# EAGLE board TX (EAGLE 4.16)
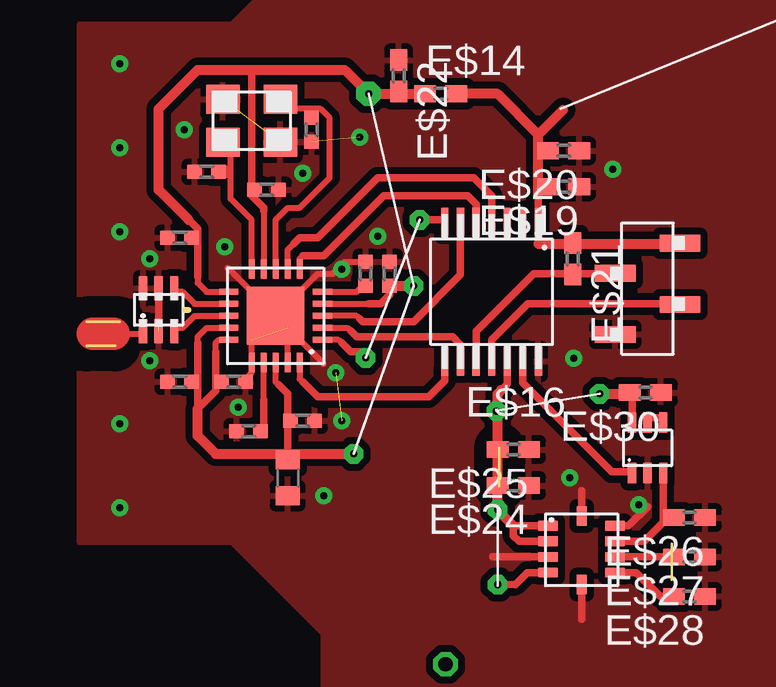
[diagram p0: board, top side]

Size 24.38 x 11.25 mm. Coordinates in mm from the lower left corner, seen from the top.
Outline: 4.12,11.25 4.25,11.25
Outline: 1.19,9.75 0,9.75
Outline: 1.38,10.75 0,10.75
Outline: 24.38,1.5 24.38,0
Outline: 17.2,5.5 17.2,3.9
Copper layers (1*16): Top 0.035mm / dielectric 1.5mm / Bottom 0.035mm
Design rules "default": minimum track width 10mil, minimum drill 24mil, track to track 8mil, track to pad 8mil, pad to pad 8mil, via to via 8mil, smd to smd 8mil, copper to edge 40mil, drill to drill 8mil, minimum pad ring 10mil, minimum via ring 8mil, stop-mask expansion 4mil, vias tented up to drill 0mil, thermal gap 10mil

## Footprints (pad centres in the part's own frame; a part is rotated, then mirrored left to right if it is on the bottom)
QFN20 = smd 0.8 x 0.26: 1 -1.95,1; 2 -1.95,0.5; 3 -1.95,0; 4 -1.95,-0.5; 5 -1.95,-1; 11 1.95,-1; 12 1.95,-0.5; 13 1.95,0; 14 1.95,0.5; 15 1.95,1 | smd 0.26 x 0.8: 6 -1,-1.95; 7 -0.5,-1.95; 8 0,-1.95; 9 0.5,-1.95; 10 1,-1.95; 16 1,1.95; 17 0.5,1.95; 18 0,1.95; 19 -0.5,1.95; 20 -1,1.95 | smd 2.4 x 2.4: EP 0,0
BALUN = smd 1 x 0.35: 1 -0.9,0.65; 2 -0.9,0; 3 -0.9,-0.65; 4 0.9,-0.65; 5 0.9,0; 6 0.9,0.65
NX3225GA = smd 1.4 x 1.2: 1 -1.2,-0.9; 2 1.2,-0.9; 3 1.2,0.9; 4 -1.2,0.9
C0402N = smd 0.6 x 0.6: 1 0.5,0; 2 -0.5,0
C0402 = smd 0.9 x 0.7: 1 -0.65,0; 2 0.65,0
C0603N = smd 0.8 x 1: 1 -0.75,0; 2 0.75,0
PW14 = smd 0.3 x 1.2: 1 -1.95,-2.9; 2 -1.3,-2.9; 3 -0.65,-2.9; 4 0,-2.9; 5 0.65,-2.9; 6 1.3,-2.9; 7 1.95,-2.9; 8 1.95,2.9; 9 1.3,2.9; 10 0.65,2.9; 11 0,2.9; 12 -0.65,2.9; 13 -1.3,2.9; 14 -1.95,2.9
1/2AA = drill 1 pad 3.1 octagon: P$1 14.7,0; P$2 -14.7,0 | drill 0.5 pad 1.27 round: P$3 -7.3,0; P$4 7.3,0 | hole 3.2: 7.3,0; -7.3,0
HEADERS4 = smd 0.7 x 1.7: P$1 1.27,1.35; P$3 -1.28,1.35; P$4 -0.03,-1.35; P$5 2.52,-1.35
KXTC9-2050 = smd 0.813 x 0.406: 1 -1.4,0.65; 2 -1.4,0; 3 -1.4,-0.65; 4 -1.4,-1.3; 6 1.4,-1.3; 7 1.4,-0.65; 8 1.4,0; 9 1.4,0.65 | smd 0.406 x 0.813: 5 0,-1.8; 10 0,1.05
SOT363 = smd 0.35 x 0.85: 1 -0.65,-1.05; 2 0,-1.05; 3 0.65,-1.05; 4 0.65,1.05; 5 0,1.05; 6 -0.65,1.05

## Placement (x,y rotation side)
E$1  [QFN20]  7.88,11 180 top
E$2  [BALUN]  3,11.25 90 top
E$3  [NX3225GA]  not placed on the board
E$4  [C0402N]  11.62,12.75 90 top
E$5  [C0402N]  not placed on the board
E$6  [C0402N]  12.62,12.75 270 top
E$7  [C0402N]  not placed on the board
E$8  [C0402N]  3.88,14.25 0 top
E$9  [C0402N]  not placed on the board
E$10  [C0402N]  6.12,8.25 0 top
E$11  [C0402N]  3.88,8.25 180 top
E$12  [C0402N]  6.75,6.19 0 top
E$13  [C0402N]  9,6.62 180 top
E$14  [C0402]  not placed on the board
E$15  [C0603N]  8.38,4.25 270 top
E$16  [PW14]  16.88,12 180 top
E$17  [1/2AA]  not placed on the board
E$18  [HEADERS4]  23.38,11.5 90 top
E$19  [C0402]  not placed on the board
E$20  [C0402]  not placed on the board
E$21  [C0402]  20.25,13.38 270 top
E$22  [C0402]  not placed on the board
E$23  [KXTC9-2050]  20.62,1.6 0 top
E$24  [C0402]  17.78,3.93 180 top
E$25  [C0402]  17.78,5.43 180 top
E$26  [C0402]  25.12,2.59 180 top
E$27  [C0402]  25.12,0.95 180 top
E$28  [C0402]  25.12,-0.69 180 top
E$29  [SOT363]  23.38,5.5 0 top
E$30  [C0402]  23.28,7.8 180 top

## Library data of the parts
E$1 E$2 E$29 = texas
E$3 = crystal
E$4-E$15 E$19-E$22 E$24-E$28 E$30 = ref-packages
E$16 = TI_MSP430_v122
E$17 = battery
E$18 = sb
E$23 = sensor

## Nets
GND: E$2.2 E$2.5 E$2.6 E$3.2 E$3.4 E$4.1 E$5.1 E$6.2 E$7.2 E$8.2 E$9.1 E$10.1 E$11.1 E$12.2 E$13.2 E$15.2 E$16.14 E$17.P$1 E$18.P$3 E$19.1 E$20.1 E$22.1 E$24.1 E$25.1 E$26.1 E$27.1 E$28.1 E$29.2 E$30.1
PWR: E$1.11
S$1: E$1.4
S$3: E$1.5
S$4: E$1.10
S$5: E$1.6
S$6: E$1.7
S$7: E$1.8
S$9: E$1.12
S$10: E$1.13
S$13: E$1.17
S$14: E$1.14 E$1.15 E$1.18 E$13.1
S$15: E$1.20
S$22: E$1.2
S$23: E$1.1

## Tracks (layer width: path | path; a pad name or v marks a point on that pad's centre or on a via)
GND  (via drill 0.3)  (5 unrouted)
  Top 0.254: 8.38,10.5 9.88,9 | 8.38,10.5 5.88,13 | E$4.1 10.75,13.25 10.25,12.75 9.62,12.75 6.88,10 6.88,8.62 6.62,8.38 E$10.1 | 8.38,9.25 8.38,10.5
  Top 0.305: 3,10.75 3,11.75 | 20.62,2.9 20.62,3.7 | 20.62,-1.65 20.62,-0.35 | 21.93,2.25 22.57,2.25 23.38,3.05 | 16.93,0.95 19.32,0.95
  other vias: 9,16.94 2.62,9.12 2.62,13.38 10.62,6.62 10.38,8.62 6.31,7.19 10.62,12.94 5.75,13.88 12.12,14.31 4.06,18.75 1.38,14.5 11.38,18.44 1.38,3 1.38,21.5 23,3.12 9.88,3.5 20.3,9.23 21.93,17.1 1.38,6.5 1.38,18 20.12,4.25
  pour Top (isolate 0.305): 58.13,-8.6 9.88,-8.6 9.88,-2.25 6.06,1.56 -0.29,1.56 -0.29,23.15 6.06,23.15 9.88,26.96 9.88,26.96 9.88,33.31 58.13,33.31 58.13,26.96 58.13,-2.25
PWR
  Top 0.254: 7.38,15.38 7.38,12.88 | E$1.11 5,12 4.62,12.38 4.62,12.62
  Top 0.305: 7.38,15.38 7.38,15.5 6.88,16 6.88,21.25 | 4.25,15 4.62,14.62 4.62,12.62
  Top 0.406: 13.88,20.25 11.75,20.25 10.75,21.25 6.88,21.25 4.62,21.25 3,19.62 3,16.25 4.25,15
S$1  (via drill 0.3 pad 0.81)
  Top 0.254: E$1.4 11.75,11.5
  Top 0.305: 12.62,12.25 12.62,11.88 12.25,11.5 11.75,11.5
  Top 0.406: 12.62,12.25 v13.62,12.25
S$2  (via drill 0.6)
  other vias: 14.96,-3.52
S$3
  Top 0.254: E$1.5 11.25,12 11.5,12.25 11.62,12.25
S$4
  Top 0.254: E$1.10 6.88,15 6,15.88 6,18.12
S$5
  Top 0.254: E$1.6 8.88,13.38 9,13.5
  Top 0.305: 9,13.5 9.88,13.5 12.38,16 15.88,16 16.23,15.65 16.23,15
S$6
  Top 0.254: E$1.7 8.38,13.75 8.62,14
  Top 0.305: 8.62,14 8.88,14.25 9.62,14.25 12.12,16.75 16.12,16.75 16.88,16 16.88,15.12
S$7
  Top 0.254: E$1.8 7.88,15 8.38,15.5 8.88,15.5 10.12,16.75 10.12,19.25 9.75,19.62 8.38,19.62
S$8
  Top 0.406: 15.5,20.25 17.12,20.25 18.82,18.55 | 18.82,16 18.82,18.55 | 18.82,18.55 19.85,19.57
S$9
  Top 0.254: E$1.12 4.5,11.5 4,12 3.62,12
S$10
  Top 0.254: E$1.13 4.5,11 4,10.5 3.62,10.5
S$11
  Top 0.254: 1.12,10.25 2.25,10.25
  Top 1.36: 1.12,10.25 0.25,10.25
S$12  (via drill 0.3 pad 0.81)
  other vias: 11.12,5.25
S$13
  Top 0.254: 7.38,7.5 E$1.17
  Top 0.305: 7.38,6.25 7.38,7.5
S$14
  Top 0.254: 8,8.12 7.88,8.25 E$1.18 | E$1.15 5.5,10 5.38,9.88 5.38,9.5 | E$1.14 5,10.5 4.62,10.12 4.62,9.88 | 8.38,7.62 8.38,7.75
  Top 0.305: 8.38,7.75 8,8.12 | 8.38,6.5 8.38,7.62 | 5.38,9.5 5.38,7.88 4.62,7.12 4.62,9.88 | 8.38,5.25 8.38,6.5 | 8.38,6.5 E$13.1
  Top 0.406: 11.12,5.25 8.38,5.25 5.38,5.25 4.62,6 4.62,7.12
S$15
  Top 0.254: E$1.20 8.88,8.38 9,8.25
  Top 0.305: 9,8.25 9.62,7.62 14.25,7.62 14.93,8.3 14.93,8.88
S$16
  Top 0.305: 22.15,12.75 18.62,12.75 16.23,10.35 16.23,9.38
S$17
  Top 0.305: 24.38,11.5 18.38,11.5 16.88,10 16.88,9.5
S$18
  Top 0.305: 18.82,14 18.82,16
  Top 0.406: 18.82,14 24.88,14
S$19  (via drill 0.3 pad 1.02)
  other vias: 11.75,20.25
S$20
  Top 0.254: 9.88,11 11.25,11 11.38,10.88
  Top 0.305: 11.38,10.88 11.5,10.75 13.62,10.75 15.57,12.7 15.57,14.62
S$21  (via drill 0.3 pad 0.81)
  Top 0.305: 22.73,7.75 22.73,6.5
  Top 0.406: v21.38,7.75 22.73,7.75
S$22
  Top 0.254: E$1.2 10.88,10.5 11,10.38
  Top 0.305: 11,10.38 11.25,10.12 15.25,10.12 15.57,9.8 15.57,9.38
S$23
  Top 0.254: E$1.1 10.5,10 10.62,9.88
  Top 0.305: 10.62,9.88 11,9.5 11.38,9.5 11.62,9.25
S$24  (via drill 0.3 pad 0.81)
  Top 0.305: v13.88,15 14.88,15
S$25
  Top 0.305: 21.93,1.6 23.23,1.6 24.09,2.47 24.64,2.47
S$27
  Top 0.305: 22.17,0.95 24.72,0.95
S$28
  Top 0.305: 19.32,0.3 18.35,0.3 17.85,-0.2 17.11,-0.19
S$29  (via drill 0.6)
  other vias: 14.96,28.23
S$30
  Top 0.305: 21.93,0.3 22.9,0.3 23.89,-0.69 24.52,-0.69
S$31  (via drill 0.6)
  other vias: 53.05,28.23
S$32  (via drill 0.6)
  other vias: 53.05,-3.52
S$33
  Top 0.305: 17.78,2.25 17.78,1.84 18.02,1.6 19.32,1.6 | 17.27,7.9 17.52,8.15 17.52,8.93
  Top 0.406: 17.78,2.25 17.13,2.9 17.13,2.93 17.12,7.75 17.27,7.9
S$34
  Top 0.305: 17.86,2.25 19.32,2.25
S$35  (via drill 0.3 pad 0.81)
  other vias: 11.62,9.25
S$36  (via drill 0.3 pad 0.81)  (1 unrouted)
  other vias: 17.12,-0.2 17.12,2.93
S$37
  Top 0.305: 18.18,8.68 18.18,8.2 21.88,4.5 22.62,4.5
S$39
  Top 0.305: 24,6.75 23.5,6.75
S$40
  Top 0.305: 24.02,2.5 24.02,4.5
S$41  (via drill 0.3 pad 0.81)
  other vias: 17.07,7.03
(copper drawn outside any net)
  shapes: Top area x1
